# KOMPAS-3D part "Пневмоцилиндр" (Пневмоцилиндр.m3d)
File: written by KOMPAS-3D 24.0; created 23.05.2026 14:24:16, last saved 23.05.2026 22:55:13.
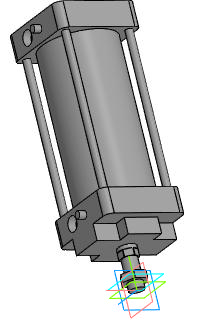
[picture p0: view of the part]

Document properties: Автор: R2D2; Полное имя файла: E:\Работа\Зайцев\GVKR1331E-1W-Fb-2P Задвижка шиберная DN.ru Ду50-300 Ру16-10-6\исходные материалы\DN125\Пневмоцилиндр.m3d

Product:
- Part/product: Пневмоцилиндр
    Масса: 20.781987

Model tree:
1. Эскиз:1
2. Элемент выдавливания:1
3. Смещенная плоскость:1
4. Эскиз:2
5. Элемент выдавливания:2
6. Эскиз:3  (with: Грань.Элемент выдавливания:1)
7. Элемент выдавливания:3
8. Эскиз:4  (with: Грань.Элемент выдавливания:3)
9. Элемент выдавливания:4  (with: Грань.Элемент выдавливания:3)
     Расстояние 2 = 9; Смещение 2 = 5
10. Эскиз:5  (with: Грань.Элемент выдавливания:3)
11. Элемент выдавливания:5
12. Эскиз:6  (with: Грань.Элемент выдавливания:5)
13. Элемент выдавливания:6
14. Эскиз:7  (with: Грань.Элемент выдавливания:6)
15. Элемент выдавливания:7
16. Эскиз:8  (with: Грань.Элемент выдавливания:7, Ребро.Элемент выдавливания:6)
17. Элемент выдавливания:8
18. Эскиз:9  (with: Грань.Элемент выдавливания:6, Вершина.Элемент выдавливания:8)
19. Элемент выдавливания:9  (with: Грань.Элемент выдавливания:8)
     Расстояние 1 = 203
20. Массив по концентрической сетке:1  (with: Элемент выдавливания:9, Эскиз:9)  (4 pattern instances)
     Шаг 2 = 360
21. Скругление:1  (with: Ребро.Элемент выдавливания:6, Ребро.Элемент выдавливания:8)
     Радиус = 10
22. Эскиз:10  (with: Грань.Элемент выдавливания:5, Ребро.Элемент выдавливания:6, Ребро.Элемент выдавливания:8)
23. Элемент выдавливания:10
     Расстояние 2 = 3.29029e-05
24. Эскиз:11  (with: Грань.Элемент выдавливания:5, Ребро.Элемент выдавливания:10)
25. Элемент выдавливания:11
     Расстояние 1 = 141316
26. Эскиз:12  (with: Ребро.Элемент выдавливания:6, Ребро.Элемент выдавливания:5)
27. Элемент выдавливания:12

Expressions: k/2; c-2*g+x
